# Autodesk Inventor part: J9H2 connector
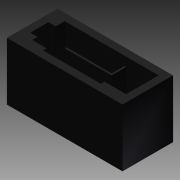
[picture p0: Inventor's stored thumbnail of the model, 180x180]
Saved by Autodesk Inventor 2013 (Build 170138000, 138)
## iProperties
Company: Autodesk Inc.
Created: 2005-12
Part Number: J9H2 connector
Document SubType Name: Modeling
Designer: Autodesk Inc.
Density: 1 g/cm^3
Mass: 0.516744 g
Surface Area: 9.189 cm^2
Volume: 0.516744 cm^3
Material: Allgemein
Title: Personal Computer
Author: Autodesk Inc.
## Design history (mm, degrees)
sketch "Sketch1"
  geometry: L1 (0, 4.9)-(0, -4.9) reference; L2 (-11.2, 0)-(11.2, 0) reference; L3 (-8, 3.5)-(8, 3.5); L4 (8, 3.5)-(8, -3.5); L5 (8, -3.5)-(-8, -3.5); L6 (-8, -3.5)-(-8, 3.5)
  constraints: 8 end point, 2 parallel, 1 horizontal, 1 perpendicular, 2 other
  dimensions: "d0" = 16 distance of L3.start L3.end; "d1" = 7 distance of L5.end L3.start
extrude "Extrusion1" new body sketch "Sketch1" distance "d2" = 8; taper "d3" = 0 deg
sketch "Sketch2"
  geometry: L1 (8, 3.5)-(8, -3.5) reference; L2 (-6, 2.5)-(7, 2.5); L3 (7, 2.5)-(7, -2); L4 (7, -2)-(-6, -2); L5 (-6, -2)-(-6, 2.5); L6 (-4, -2)-(4, -2); L7 (4, -2)-(4, -2.5); L8 (4, -2.5)-(-4, -2.5); L9 (-4, -2.5)-(-4, -2); L10 (-6, 1.25)-(-7, 1.25); L11 (-7, 1.25)-(-7, -1.25); L12 (-7, -1.25)-(-6, -1.25); L13 (-6, -1.25)-(-6, 1.25); L14 (0, 4.9)-(0, -4.9) reference; L15 (-11.2, 0)-(11.2, 0) reference
  constraints: 24 end point, 6 parallel, 3 horizontal, 3 perpendicular, 2 point on line, 3 other
  dimensions: "d4" = 14 distance between parallel lines of L3 L11; "d5" = 1 distance of L10.start L10.end; "d6" = 2.5 distance of L10.end L11.end; "d7" = 0.5 distance of L8.end L6.start; "d8" = 5 distance between parallel lines of L8 L2; "d9" = 1 distance between parallel lines of L1 L3; "d10" = 8 distance of L7.end L8.end
extrude "Extrusion2" cut sketch "Sketch2" distance "d11" = 6; taper "d12" = 0 deg
sketch "Sketch3"
  geometry: L1 (0, 4.9)-(0, -4.9) reference; L2 (-11.2, 0)-(11.2, 0) reference; L3 (-3.25, 0)-(3.25, 0); L4 (3.25, 0)-(3.25, -0.25); L5 (3.25, -0.25)-(-3.25, -0.25); L6 (-3.25, -0.25)-(-3.25, 0); L7 (3.25, 0)-(3, 0); L8 (3, 0)-(3, 1.75); L9 (3, 1.75)-(3.25, 1.75); L10 (3.25, 1.75)-(3.25, 0)
  constraints: 16 end point, 4 parallel, 2 horizontal, 2 perpendicular, 1 point on line, 1 other
  dimensions: "d13" = 6.5 distance of L4.end L5.end; "d14" = 2 distance between parallel lines of L5 L9; "d15" = 0.25 distance between parallel lines of L3 L5 (= d16); "d16" = 0.25 distance between parallel lines of L10 L8
extrude "Extrusion3" join sketch "Sketch3" distance "d17" = 5.5; taper "d18" = 0 deg
sketch "Sketch4"
  geometry: L1 (-3.25, 0)-(3, 0) reference; L2 (3, 0)-(3, 1.75) reference; L3 (2.7, 0)-(2.3, 0); L4 (2.3, 0)-(2.3, 0.5); L5 (2.3, 0.5)-(2.7, 0.5); L6 (2.7, 0.5)-(2.7, 0)
  constraints: 8 end point, 2 parallel, 1 horizontal, 1 perpendicular, 1 point on line
  dimensions: "d19" = 0.3 distance between parallel lines of L2 L6; "d20" = 0.4 distance of L4.end L5.end; "d21" = 0.5 distance of L3.end L4.end
extrude "Extrusion4" cut sketch "Sketch4" distance "d22" = 0.5; taper "d23" = 0 deg
pattern_linear "Rectangular Pattern1" dims "d26" = 1
body "Solid1"
